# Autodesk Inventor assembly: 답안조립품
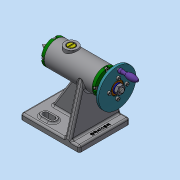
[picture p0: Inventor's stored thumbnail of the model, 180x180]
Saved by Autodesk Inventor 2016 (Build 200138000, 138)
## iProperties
Created: 2019-10
Part Number: 답안조립품
Material: 일반
Document SubType Name: Assembly
Designer: Administrator
Author: Administrator
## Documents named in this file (18)
- C:\Users\Administrator\Desktop\491004V1008\답안조립품.iam
- C:\Users\Administrator\Desktop\491004V1008\본체.ipt
- C:\Users\Administrator\Desktop\491004V1008\나사.ipt
- C:\Users\Administrator\Desktop\491004V1008\나사축.ipt
- C:\Users\Administrator\Desktop\491004V1008\너트 M8.ipt
- C:\Users\Administrator\Desktop\491004V1008\돌림판.ipt
- C:\Users\Administrator\Desktop\491004V1008\멈춤나사 M3.ipt
- C:\Users\Administrator\Desktop\491004V1008\볼트 M3.ipt
- C:\Users\Administrator\Desktop\491004V1008\부시.ipt
- C:\Users\Administrator\Desktop\491004V1008\센터.ipt
- C:\Users\Administrator\Desktop\491004V1008\센터홀더.ipt
- C:\Users\Administrator\Desktop\491004V1008\슬리브.ipt
- C:\Users\Administrator\Desktop\491004V1008\와셔.ipt
- C:\Users\Administrator\Desktop\491004V1008\중공축.ipt
- C:\Users\Administrator\Desktop\491004V1008\커버.ipt
- C:\Users\Administrator\Desktop\491004V1008\키 4 x 4 x 10.ipt
- C:\Users\Administrator\Desktop\491004V1008\플랜지.ipt
- C:\Users\Administrator\Desktop\491004V1008\핸들.ipt
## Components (2 placed, 2 different names)
1. 플랜지:1 — 각도:2
2. 핸들:1 — 플러쉬:1
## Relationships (2: Angle 1, Flush 1)
- 각도:2 [Angle]: 플랜지:1
- 플러쉬:1 [Flush]: 핸들:1
